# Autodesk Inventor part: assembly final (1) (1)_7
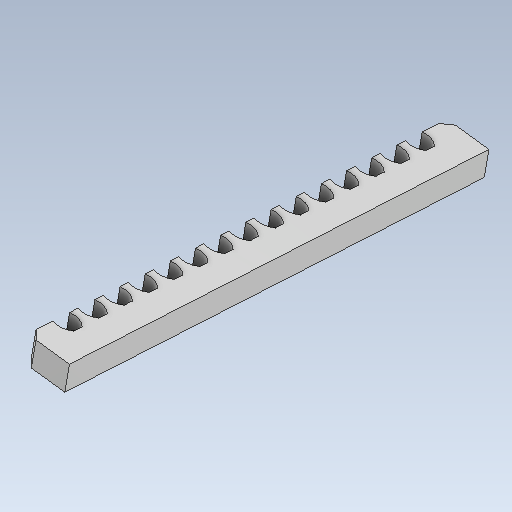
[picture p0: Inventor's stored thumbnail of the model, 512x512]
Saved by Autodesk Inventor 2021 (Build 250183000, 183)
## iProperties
Created: 2021-07
Part Number: assembly final (1) (1)_7
Material: Generic
Document SubType Name: Modeling
Designer: TARUN
Density: 1 g/cm^3
Appearance: Default
Author: TARUN
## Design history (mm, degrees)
feature "Base1"
body "Solid1"
